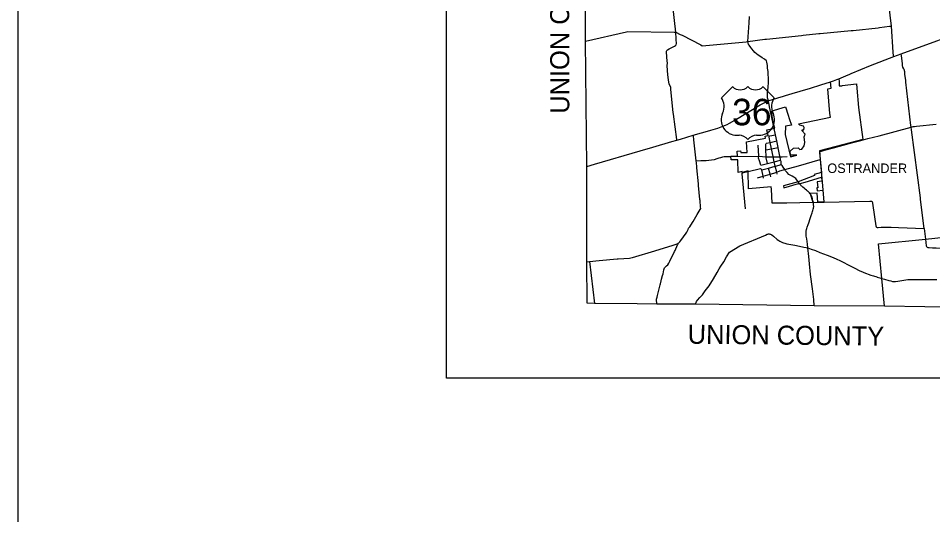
# Model space of a CAD drawing. Extents: x 1729596 to 1925846, y 659247 to 911751.
# Drawn here: x 1729596 to 1777664, y 807237 to 833354 of the extents above; entities that cross this region are included whole.
import ezdxf

# ---------------------------------------------------------------- set-up
doc = ezdxf.new("R2010")
doc.units = 0
for name, color, linetype in [('GM_X_Adjacent_County_Text', 7, 'Continuous'), ('GM_X_City_Street', 7, 'Continuous'), ('GM_X_Corporation', 7, 'Continuous'), ('GM_X_Corporation_Text', 7, 'Continuous'), ('GM_X_County', 7, 'Continuous'), ('GM_X_County_Road', 7, 'Continuous'), ('GM_X_Township', 7, 'Continuous'), ('GM_X_Township_Road', 7, 'Continuous'), ('GM_X_US_Route', 7, 'Continuous'), ('GM_X_US_Shield', 7, 'Continuous'), ('SC_Scratch1', 7, 'Continuous'), ('SH_Data', 7, 'Continuous')]:
    doc.layers.add(name, color=color, linetype=linetype)

msp = doc.modelspace()

# ---------------------------------------------------------------- linework, layer by layer
at = {"layer": 'GM_X_City_Street'}
for points in [[(1769548, 826540), (1769543, 826564), (1769471, 826898), (1769401, 827230), (1769337, 827561)], [(1768886, 826738), (1768901, 826766), (1768919, 826777), (1769120, 826820), (1769471, 826898)], [(1769271, 826089), (1769192, 826491), (1769120, 826820), (1769061, 827104), (1769063, 827130)], [(1769063, 827130), (1769074, 827149), (1769096, 827162), (1769401, 827230)], [(1768521, 826098), (1768485, 826682)], [(1768917, 826017), (1768915, 826027), (1768908, 826068), (1768906, 826074), (1768900, 826435), (1768886, 826738)], [(1768900, 826435), (1769192, 826491), (1769543, 826564)], [(1769638, 826055), (1769635, 826070), (1769630, 826095), (1769548, 826540)], [(1767048, 826083), (1768521, 826098), (1768908, 826068), (1769243, 826069)], [(1768631, 825627), (1768553, 825848), (1768504, 826001), (1768521, 826098)], [(1768631, 825627), (1768976, 825712), (1768986, 825715), (1769323, 825803), (1769324, 825803)], [(1768976, 825712), (1768917, 826017)], [(1769243, 826069), (1769276, 826069), (1769384, 826070), (1769635, 826070), (1769648, 826070), (1769695, 826071)], [(1769389, 825571), (1769333, 825805), (1769332, 825808), (1769276, 826069), (1769273, 826081), (1769271, 826089)], [(1769324, 825803), (1769328, 825804), (1769333, 825805), (1769670, 825894)], [(1769695, 825787), (1769694, 825812), (1769670, 825894), (1769663, 825920), (1769638, 826055)], [(1769695, 826071), (1769754, 826072), (1770018, 826076)], [(1769819, 825385), (1769885, 825404), (1770603, 825592), (1771745, 825922), (1771760, 825927)], [(1767958, 825301), (1768618, 825455), (1768683, 825374)], [(1768683, 825374), (1769033, 825464), (1769389, 825568), (1769411, 825574), (1769415, 825576)], [(1768778, 824942), (1768755, 825050), (1768683, 825374)], [(1769155, 825004), (1769115, 825152), (1769033, 825464)], [(1769487, 825158), (1769463, 825258), (1769389, 825568), (1769389, 825571)], [(1769415, 825576), (1769701, 825659)], [(1769421, 825240), (1769463, 825258), (1769634, 825332), (1769819, 825385)], [(1769913, 825363), (1769885, 825404), (1769808, 825525), (1769748, 825613), (1769701, 825659), (1769695, 825787)], [(1770586, 824748), (1770461, 824918), (1770410, 824968), (1770357, 825002), (1770276, 825042), (1770100, 825127), (1770006, 825232), (1769933, 825332), (1769913, 825363)], [(1768454, 824965), (1768755, 825050), (1769115, 825152), (1769130, 825156), (1769417, 825238), (1769421, 825240)], [(1771274, 824046), (1771261, 824081), (1771231, 824125), (1771187, 824176), (1771155, 824206), (1771104, 824253), (1771086, 824267), (1771038, 824305), (1770959, 824368), (1770906, 824410), (1770837, 824466), (1770781, 824514), (1770756, 824540), (1770731, 824566), (1770669, 824641)]]:
    msp.add_lwpolyline(points, dxfattribs=at)
at = {"layer": 'GM_X_Corporation'}
msp.add_lwpolyline([(1769366, 827566), (1769320, 827752), (1769283, 827899), (1769224, 828187), (1769220, 828231), (1769215, 828272), (1769205, 828338), (1769201, 828357), (1769176, 828462), (1769925, 828702), (1770060, 828263), (1770118, 828088), (1770236, 827725), (1769933, 827679), (1769911, 827243), (1770190, 826064), (1770525, 826154), (1770191, 826146), (1770169, 826359), (1770338, 826528), (1770586, 826544), (1770683, 826450), (1770782, 826469), (1770909, 826645), (1770950, 826818), (1770913, 827112), (1770957, 827249), (1770807, 827429), (1770799, 827480), (1770890, 827488), (1770907, 827609), (1770873, 827670), (1770687, 827736), (1770603, 827796), (1770603, 827800), (1772285, 828146), (1772260, 828341), (1772149, 829635), (1772325, 829685), (1772294, 830004), (1772455, 830058), (1772624, 830124), (1772727, 830167), (1772729, 830156), (1772738, 830043), (1772747, 829793), (1772897, 829798), (1772896, 829824), (1773654, 829910), (1773676, 829675), (1773771, 828660), (1773998, 826974), (1773320, 826803), (1771708, 826372), (1771745, 825922), (1771812, 825233), (1771431, 825135), (1771445, 825087), (1770586, 824748), (1769828, 824539), (1769843, 824442), (1770610, 824664), (1770630, 824638), (1770690, 824658), (1770959, 824737), (1771826, 824988), (1771844, 824782), (1771593, 824744), (1771620, 824440), (1771572, 824436), (1771585, 824276), (1771886, 824304), (1771943, 823690), (1771631, 823682), (1771596, 824161), (1771226, 824142), (1771315, 823845), (1771362, 823658), (1769988, 823626), (1769225, 823627), (1769186, 824365), (1769168, 824490), (1767986, 824383), (1767957, 825326), (1767646, 825244), (1767644, 825296), (1767437, 825241), (1767416, 825906), (1767065, 825899), (1767047, 826093), (1767411, 826103), (1767388, 826357), (1767562, 826373), (1767569, 826290), (1767911, 826292), (1767884, 826859), (1768872, 827047), (1768849, 827157), (1769003, 827186), (1769016, 827165), (1769013, 827188), (1768949, 827484)], close=True, dxfattribs=at)
at = {"layer": 'GM_X_County'}
msp.add_lwpolyline([(1779378, 818146), (1775121, 818204), (1771439, 818234), (1765188, 818306), (1763158, 818312), (1762137, 818333), (1759879, 818354), (1759498, 818358), (1759475, 820549), (1759482, 825563), (1759416, 832152), (1759463, 844341), (1759463, 847793), (1759489, 848768), (1759505, 848913), (1759514, 851039), (1759526, 852942), (1759514, 856565), (1759518, 857896), (1759604, 861482)], dxfattribs=at)
at = {"layer": 'GM_X_County_Road'}
for points in [[(1764156, 832620), (1763784, 836032), (1763776, 836097), (1763123, 841759), (1763037, 842583), (1762977, 843169), (1762897, 844278), (1762874, 844646), (1762856, 846750), (1762837, 849052), (1762835, 849154), (1762790, 850103), (1762786, 850187), (1762639, 852096), (1762618, 852326)], [(1769009, 829733), (1769011, 829773), (1769024, 829932), (1769032, 830068), (1769032, 830169), (1769018, 830454), (1769007, 830555), (1768988, 830729), (1768979, 830866), (1768964, 830950), (1768943, 831036), (1768919, 831121), (1768820, 831201), (1768698, 831276), (1768581, 831360), (1768496, 831418), (1768402, 831483), (1768321, 831552), (1768247, 831643), (1768152, 831741), (1768101, 831824), (1768020, 831931), (1767988, 831971), (1767948, 832130), (1768010, 833120), (1768038, 833441)], [(1759416, 832152), (1761564, 832643), (1761642, 832660), (1764071, 832622), (1764156, 832620)], [(1764156, 832620), (1764156, 832620), (1764393, 832505), (1764487, 832460), (1765471, 831949), (1765545, 831910), (1767859, 832122), (1767948, 832130)], [(1769021, 829003), (1769009, 829062), (1768987, 829164), (1768982, 829206), (1768975, 829289), (1768974, 829357), (1768978, 829433), (1768992, 829582), (1769007, 829710), (1769009, 829733)], [(1769190, 828230), (1769089, 828689), (1769062, 828821), (1769021, 829003)], [(1769303, 827715), (1769190, 828230)], [(1771760, 825927), (1771734, 826287), (1771746, 826319), (1771765, 826340), (1771813, 826366), (1771982, 826412), (1772451, 826538), (1773457, 826810), (1773880, 826927), (1774255, 827029), (1774842, 827167), (1776532, 827627), (1776633, 827652), (1776699, 827665), (1776814, 827681), (1777839, 827790)], [(1769337, 827561), (1769303, 827715)], [(1765229, 825854), (1765111, 826962), (1765108, 827005), (1765094, 827110), (1765085, 827163), (1765076, 827196)], [(1765229, 825854), (1765477, 825865), (1765758, 825867), (1766035, 825905), (1766185, 825924), (1766330, 825985), (1766443, 826010), (1766524, 826038), (1766632, 826066), (1766709, 826074), (1767048, 826083)], [(1770669, 824641), (1770659, 824653), (1770636, 824683), (1770586, 824748)], [(1771097, 821279), (1771078, 821468), (1771041, 821753), (1771020, 821899), (1771011, 821984), (1771010, 822008), (1771010, 822073), (1771017, 822155), (1771034, 822246), (1771045, 822291), (1771066, 822361), (1771115, 822505), (1771147, 822600), (1771220, 822813), (1771272, 822970), (1771324, 823125), (1771345, 823187), (1771366, 823243), (1771386, 823312), (1771399, 823362), (1771405, 823404), (1771407, 823437), (1771406, 823562), (1771401, 823608), (1771392, 823659), (1771369, 823757), (1771343, 823853), (1771319, 823947), (1771303, 823982), (1771290, 824012), (1771275, 824042), (1771274, 824046)], [(1765188, 818306), (1765250, 818449), (1765292, 818518), (1765426, 818658), (1765567, 818807), (1765702, 819011), (1765908, 819283), (1766140, 819652), (1766332, 819971), (1766436, 820175), (1766534, 820321), (1766692, 820540), (1766826, 820796), (1766981, 821041), (1767531, 821388), (1768875, 821950), (1768969, 821988), (1769001, 821998), (1769037, 822006), (1769074, 822008), (1769110, 822003), (1769145, 821992), (1769168, 821981), (1769205, 821957), (1769287, 821892), (1769495, 821721), (1769580, 821663), (1769625, 821635), (1769698, 821594), (1769732, 821576), (1769768, 821560), (1769829, 821535), (1769893, 821517), (1770004, 821493), (1770424, 821410), (1770661, 821366), (1770886, 821321), (1771018, 821298), (1771097, 821279)], [(1771097, 821279), (1771097, 821279), (1771275, 821212), (1771494, 821130), (1771728, 821038), (1772114, 820892), (1772428, 820769), (1772627, 820685), (1772790, 820604), (1772889, 820552), (1773284, 820349), (1773532, 820220), (1773827, 820073), (1773966, 820009), (1774045, 819974), (1774178, 819920), (1774267, 819886), (1774415, 819835), (1774547, 819798), (1774723, 819744)], [(1771439, 818234), (1771411, 818565), (1771345, 819118), (1771247, 819868), (1771185, 820443), (1771145, 820816), (1771097, 821279)], [(1774723, 819744), (1774744, 819738), (1774892, 819695), (1774985, 819668), (1775128, 819627), (1775350, 819562), (1775457, 819533), (1775550, 819514), (1775598, 819506), (1775656, 819502), (1775681, 819502), (1775705, 819505), (1775822, 819523), (1776147, 819573), (1776357, 819604), (1776450, 819612), (1777089, 819612), (1777505, 819610), (1777646, 819609), (1777873, 819605)]]:
    msp.add_lwpolyline(points, dxfattribs=at)
at = {"layer": 'GM_X_Township'}
msp.add_lwpolyline([(1775121, 818204), (1774985, 819668), (1774815, 821485), (1777282, 821728), (1779745, 821996)], dxfattribs=at)
at = {"layer": 'GM_X_Township_Road'}
for points in [[(1775615, 831340), (1775603, 831383), (1775586, 831575), (1775490, 832941), (1775353, 834104), (1775241, 835291), (1775198, 835734), (1775155, 836142)], [(1764213, 826942), (1764207, 826976), (1764037, 828304), (1764025, 828401), (1763904, 829610), (1763894, 829705), (1763803, 829899), (1763787, 829999), (1763773, 830109), (1763746, 830381), (1763711, 830858), (1763715, 831003), (1763707, 831098), (1763670, 831571), (1763665, 831625), (1763687, 831661), (1763731, 831691), (1763811, 831746), (1764091, 831895), (1764144, 831924), (1764176, 831950), (1764194, 832033), (1764182, 832243), (1764176, 832345), (1764161, 832556), (1764156, 832620)], [(1767948, 832130), (1768838, 832248), (1768926, 832260), (1770764, 832451), (1770846, 832459), (1771686, 832553), (1771754, 832560), (1773384, 832710), (1773488, 832719), (1774800, 832859), (1774870, 832867), (1775395, 832930), (1775490, 832941)], [(1777221, 822293), (1777028, 823812), (1777016, 823904), (1776553, 827493), (1776532, 827627), (1776520, 827705), (1776256, 829999), (1776244, 830093), (1776203, 830392), (1776191, 830540), (1776185, 830582), (1776180, 830618), (1776172, 830646), (1776152, 830691), (1776100, 830790), (1776083, 830874), (1776071, 830977), (1776026, 831382), (1776007, 831488)], [(1765464, 823415), (1765464, 823416), (1765435, 823761), (1765430, 823819), (1765359, 824555), (1765350, 824644), (1765268, 825485), (1765262, 825547), (1765239, 825757), (1765229, 825854)], [(1771967, 823673), (1771911, 824322), (1771760, 825927)], [(1767821, 823327), (1767644, 825166), (1767655, 825211), (1767700, 825236), (1767958, 825301)], [(1764300, 821518), (1764365, 821601), (1764418, 821669), (1764702, 822050), (1764739, 822100), (1764741, 822102), (1764806, 822246), (1764833, 822307), (1764889, 822387), (1765035, 822607), (1765070, 822660), (1765282, 823025), (1765334, 823113), (1765443, 823294), (1765470, 823340), (1765464, 823415)], [(1771392, 823659), (1771967, 823673), (1772750, 823692), (1774351, 823727), (1774447, 823728), (1774465, 823723), (1774487, 823706), (1774504, 823624), (1774603, 822910), (1774666, 822431), (1774684, 822387), (1774711, 822363), (1774741, 822354), (1774791, 822352), (1774948, 822364), (1775016, 822367), (1775479, 822358), (1775865, 822355), (1777221, 822293), (1777282, 821728), (1777323, 821374), (1777332, 821354), (1777347, 821333), (1777357, 821325), (1777369, 821317)], [(1759475, 820549), (1759627, 820564), (1760130, 820613), (1761077, 820691), (1761137, 820697), (1761717, 820740), (1761791, 820745), (1761891, 820777), (1763055, 821123), (1763108, 821139), (1763965, 821405), (1764026, 821424), (1764225, 821492), (1764300, 821518)], [(1763158, 818312), (1763147, 818574), (1763154, 818635), (1763171, 818685), (1763196, 818763), (1763338, 819326), (1763352, 819382), (1763392, 819536), (1763415, 819623), (1763466, 819828), (1763489, 819918), (1763536, 820124), (1763557, 820217), (1763674, 820324), (1763743, 820387), (1763794, 820479), (1763843, 820571), (1764098, 821093), (1764122, 821141), (1764257, 821427), (1764300, 821518)], [(1777369, 821317), (1777379, 821311), (1777403, 821302), (1777475, 821295), (1777649, 821286), (1777837, 821276), (1778492, 821239), (1779839, 821168), (1779960, 820119), (1779977, 820076), (1780006, 820041), (1780064, 819993), (1780157, 819926), (1780385, 819739), (1780466, 819673), (1780509, 819649)], [(1759627, 820564), (1759879, 818354)]]:
    msp.add_lwpolyline(points, dxfattribs=at)
at = {"layer": 'GM_X_US_Route'}
for points in [[(1773271, 830397), (1773379, 830444), (1774387, 830877), (1775615, 831340), (1776007, 831488), (1777883, 832171), (1778258, 832305), (1778909, 832522), (1779520, 832725), (1780843, 833166), (1781136, 833265), (1781140, 833266)], [(1772294, 830004), (1772294, 830004), (1772449, 830056), (1772624, 830124), (1772727, 830167), (1772737, 830171)], [(1772737, 830171), (1773219, 830375), (1773271, 830397)], [(1769924, 829291), (1770273, 829395), (1770694, 829522), (1771235, 829684)], [(1771235, 829684), (1771786, 829850), (1772294, 830004)], [(1765996, 827463), (1766362, 827573), (1766631, 827672), (1766764, 827729), (1766851, 827770), (1766978, 827835), (1767259, 827995), (1768587, 828797), (1768776, 828894), (1769021, 829003), (1769302, 829103), (1769694, 829222), (1769773, 829246)], [(1769773, 829246), (1769924, 829291)], [(1759482, 825563), (1759881, 825677), (1762279, 826378), (1762950, 826573), (1763952, 826869), (1764213, 826942), (1764404, 826999), (1765076, 827196), (1765952, 827450), (1765996, 827463)]]:
    msp.add_lwpolyline(points, dxfattribs=at)
at = {"layer": 'GM_X_US_Shield'}
for p, q in [((1767134, 829755), (1766554, 829175)), ((1767134, 829755), (1766554, 829175)), ((1769338, 829175), (1768758, 829755)), ((1769338, 829175), (1768758, 829755)), ((1767366, 827203), (1767482, 827203)), ((1767366, 827203), (1767482, 827203)), ((1768410, 827203), (1768526, 827203)), ((1768410, 827203), (1768526, 827203))]:
    msp.add_line(p, q, dxfattribs=at)
for centre, radius, start, end in [((1767540, 830170), 580, 225.573, 314.427), ((1767540, 830170), 580, 225.573, 314.427), ((1768352, 830170), 580, 225.573, 314.427), ((1768352, 830170), 580, 225.573, 314.427), ((1765889, 828709), 812, 334.5471, 35.0009), ((1765889, 828709), 812, 334.5471, 35.0009), ((1770003, 828709), 812, 144.9991, 205.4529), ((1770003, 828709), 812, 144.9991, 205.4529), ((1767357, 828015), 812, 154.8319, 270.6383), ((1767357, 828015), 812, 154.8319, 270.6383), ((1768535, 828015), 812, 269.3617, 25.1681), ((1768535, 828015), 812, 269.3617, 25.1681), ((1767482, 826623), 580, 36.8699, 90), ((1767482, 826623), 580, 36.8699, 90), ((1768410, 826623), 580, 90, 143.1301), ((1768410, 826623), 580, 90, 143.1301)]:
    msp.add_arc(centre, radius, start, end, dxfattribs=at)
at = {"layer": 'SC_Scratch1'}
msp.add_lwpolyline([(1729596, 899996), (1925846, 899996), (1925846, 765496), (1729596, 765496)], close=True, dxfattribs=at)
at = {"layer": 'SH_Data'}
for p, q in [((1752099, 814428), (1752099, 890928)), ((1828599, 814428), (1752099, 814428))]:
    msp.add_line(p, q, dxfattribs=at)

# ---------------------------------------------------------------- texts
at = {"layer": 'GM_X_Adjacent_County_Text'}
for rotation, p in [(90.0931, (1758562, 828334)), (359.4149, (1764781, 816235))]:
    msp.add_text('UNION COUNTY', height=1000, rotation=rotation, dxfattribs=at).set_placement(p)
at = {"layer": 'GM_X_Corporation_Text'}
msp.add_text('OSTRANDER', height=500, rotation=0, dxfattribs=at).set_placement((1772122, 825215))
at = {"layer": 'GM_X_US_Shield'}
msp.add_text('36', height=1392.2, dxfattribs=at).set_placement((1767119, 827725))
msp.add_text('36', height=1392.2, dxfattribs=at).set_placement((1767119, 827725))

doc.saveas('drawing.dxf')
